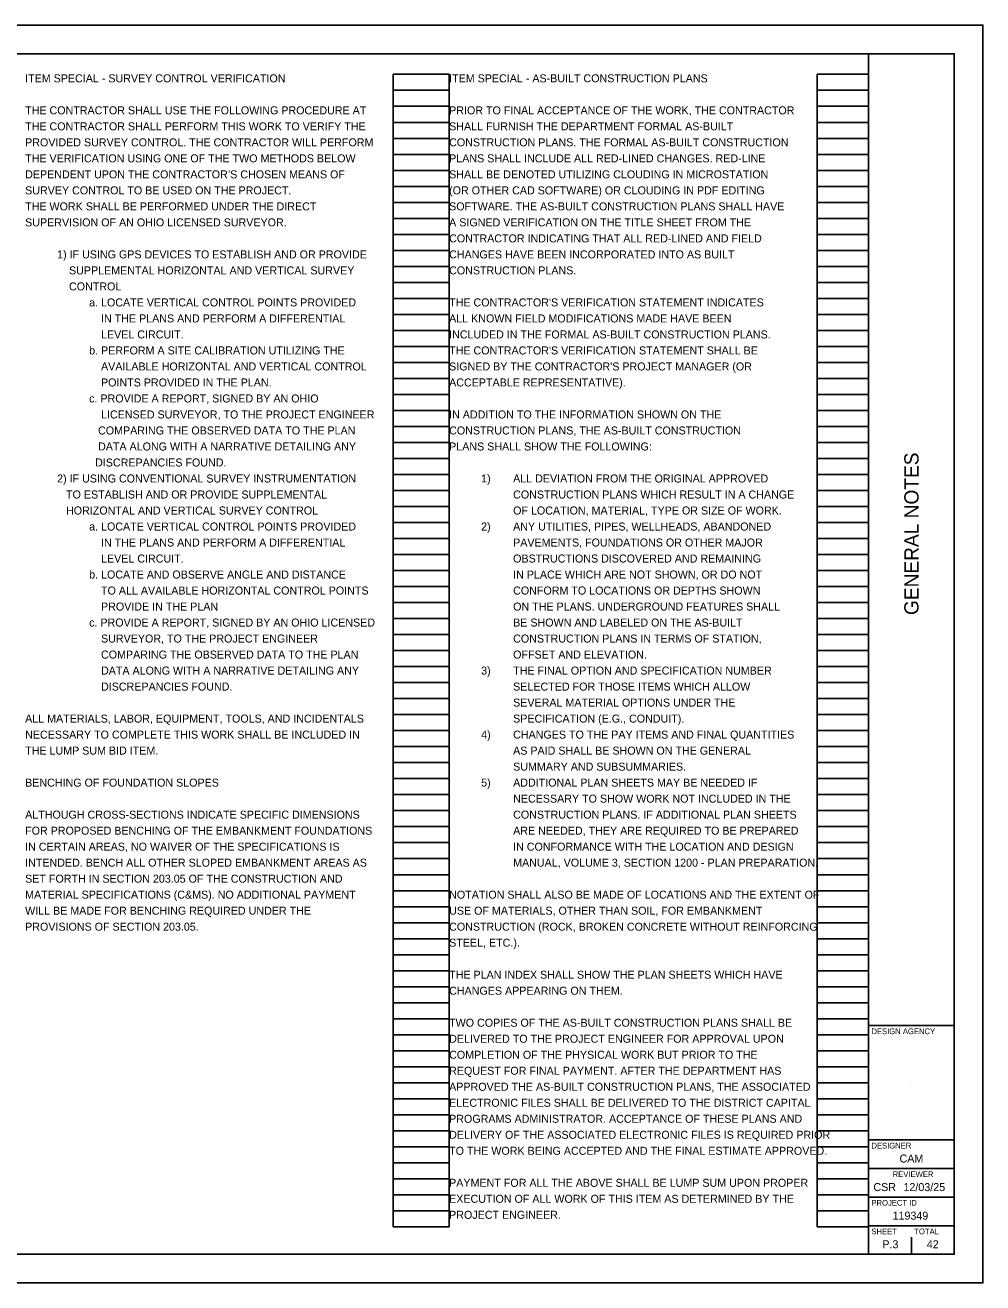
# Model space of a CAD drawing. Extents: x 0 to 34, y 0 to 22.
# Drawn here: x 17.24 to 34, y 0 to 22 of the extents above; entities that cross this region are included whole.
import ezdxf

# ---------------------------------------------------------------- set-up
doc = ezdxf.new("R2010")
doc.units = 0
for name, color, linetype in [('SH_Border', 7, 'Continuous'), ('SH_Cut_Line', 7, 'Continuous'), ('SH_Data', 7, 'Continuous'), ('SH_Text', 7, 'Continuous')]:
    doc.layers.add(name, color=color, linetype=linetype)

msp = doc.modelspace()

# ---------------------------------------------------------------- linework, layer by layer
at = {"layer": 'SH_Border'}
for p, q in [((32, 0.5), (32, 21.5)), ((32, 4.5), (33.5, 4.5)), ((32, 2.5), (33.5, 2.5)), ((32, 2), (33.5, 2)), ((32, 1.5), (33.5, 1.5)), ((32, 1), (33.5, 1))]:
    msp.add_line(p, q, dxfattribs=at)
msp.add_lwpolyline([(1.5, 21.5), (33.5, 21.5), (33.5, 0.5), (1.5, 0.5)], close=True, dxfattribs=at)
at = {"layer": 'SH_Cut_Line'}
msp.add_lwpolyline([(0, 0), (34, 0), (34, 22), (0, 22)], close=True, dxfattribs=at)
at = {"layer": 'SH_Data'}
for p, q in [((23.68, 0.98), (23.68, 21.14)), ((23.68, 21.14), (24.66, 21.14)), ((24.66, 0.98), (24.66, 21.14)), ((31.1, 0.98), (31.1, 21.14)), ((31.1, 21.14), (32, 21.14)), ((32, 0.98), (32, 21.14)), ((23.68, 20.86), (24.66, 20.86)), ((31.1, 20.86), (32, 20.86)), ((23.68, 20.58), (24.66, 20.58)), ((31.1, 20.58), (32, 20.58)), ((23.68, 20.3), (24.66, 20.3)), ((31.1, 20.3), (32, 20.3)), ((23.68, 20.02), (24.66, 20.02)), ((31.1, 20.02), (32, 20.02)), ((23.68, 19.74), (24.66, 19.74)), ((31.1, 19.74), (32, 19.74)), ((23.68, 19.46), (24.66, 19.46)), ((31.1, 19.46), (32, 19.46)), ((23.68, 19.18), (24.66, 19.18)), ((31.1, 19.18), (32, 19.18)), ((23.68, 18.9), (24.66, 18.9)), ((31.1, 18.9), (32, 18.9)), ((23.68, 18.62), (24.66, 18.62)), ((31.1, 18.62), (32, 18.62)), ((23.68, 18.34), (24.66, 18.34)), ((31.1, 18.34), (32, 18.34)), ((23.68, 18.06), (24.66, 18.06)), ((31.1, 18.06), (32, 18.06)), ((23.68, 17.78), (24.66, 17.78)), ((31.1, 17.78), (32, 17.78)), ((23.68, 17.5), (24.66, 17.5)), ((31.1, 17.5), (32, 17.5)), ((23.68, 17.22), (24.66, 17.22)), ((31.1, 17.22), (32, 17.22)), ((23.68, 16.94), (24.66, 16.94)), ((31.1, 16.94), (32, 16.94)), ((23.68, 16.66), (24.66, 16.66)), ((31.1, 16.66), (32, 16.66)), ((23.68, 16.38), (24.66, 16.38)), ((31.1, 16.38), (32, 16.38)), ((23.68, 16.1), (24.66, 16.1)), ((31.1, 16.1), (32, 16.1)), ((23.68, 15.82), (24.66, 15.82)), ((31.1, 15.82), (32, 15.82)), ((23.68, 15.54), (24.66, 15.54)), ((31.1, 15.54), (32, 15.54)), ((23.68, 15.26), (24.66, 15.26)), ((31.1, 15.26), (32, 15.26)), ((23.68, 14.98), (24.66, 14.98)), ((31.1, 14.98), (32, 14.98)), ((23.68, 14.7), (24.66, 14.7)), ((31.1, 14.7), (32, 14.7)), ((23.68, 14.42), (24.66, 14.42)), ((31.1, 14.42), (32, 14.42)), ((23.68, 14.14), (24.66, 14.14)), ((31.1, 14.14), (32, 14.14)), ((23.68, 13.86), (24.66, 13.86)), ((31.1, 13.86), (32, 13.86)), ((23.68, 13.58), (24.66, 13.58)), ((31.1, 13.58), (32, 13.58)), ((23.68, 13.3), (24.66, 13.3)), ((31.1, 13.3), (32, 13.3)), ((23.68, 13.02), (24.66, 13.02)), ((31.1, 13.02), (32, 13.02)), ((23.68, 12.74), (24.66, 12.74)), ((31.1, 12.74), (32, 12.74)), ((23.68, 12.46), (24.66, 12.46)), ((31.1, 12.46), (32, 12.46)), ((23.68, 12.18), (24.66, 12.18)), ((31.1, 12.18), (32, 12.18)), ((23.68, 11.9), (24.66, 11.9)), ((31.1, 11.9), (32, 11.9)), ((23.68, 11.62), (24.66, 11.62)), ((31.1, 11.62), (32, 11.62)), ((23.68, 11.34), (24.66, 11.34)), ((31.1, 11.34), (32, 11.34)), ((23.68, 11.06), (24.66, 11.06)), ((31.1, 11.06), (32, 11.06)), ((23.68, 10.78), (24.66, 10.78)), ((31.1, 10.78), (32, 10.78)), ((23.68, 10.5), (24.66, 10.5)), ((31.1, 10.5), (32, 10.5)), ((23.68, 10.22), (24.66, 10.22)), ((31.1, 10.22), (32, 10.22)), ((23.68, 9.94), (24.66, 9.94)), ((31.1, 9.94), (32, 9.94)), ((23.68, 9.66), (24.66, 9.66)), ((31.1, 9.66), (32, 9.66)), ((23.68, 9.38), (24.66, 9.38)), ((31.1, 9.38), (32, 9.38)), ((23.68, 9.1), (24.66, 9.1)), ((31.1, 9.1), (32, 9.1)), ((23.68, 8.82), (24.66, 8.82)), ((31.1, 8.82), (32, 8.82)), ((23.68, 8.54), (24.66, 8.54)), ((31.1, 8.54), (32, 8.54)), ((23.68, 8.26), (24.66, 8.26)), ((31.1, 8.26), (32, 8.26)), ((23.68, 7.98), (24.66, 7.98)), ((31.1, 7.98), (32, 7.98)), ((23.68, 7.7), (24.66, 7.7)), ((31.1, 7.7), (32, 7.7)), ((23.68, 7.42), (24.66, 7.42)), ((31.1, 7.42), (32, 7.42)), ((23.68, 7.14), (24.66, 7.14)), ((31.1, 7.14), (32, 7.14)), ((23.68, 6.86), (24.66, 6.86)), ((31.1, 6.86), (32, 6.86)), ((23.68, 6.58), (24.66, 6.58)), ((31.1, 6.58), (32, 6.58)), ((23.68, 6.3), (24.66, 6.3)), ((31.1, 6.3), (32, 6.3)), ((23.68, 6.02), (24.66, 6.02)), ((31.1, 6.02), (32, 6.02)), ((23.68, 5.74), (24.66, 5.74)), ((31.1, 5.74), (32, 5.74)), ((23.68, 5.46), (24.66, 5.46)), ((31.1, 5.46), (32, 5.46)), ((23.68, 5.18), (24.66, 5.18)), ((31.1, 5.18), (32, 5.18)), ((23.68, 4.9), (24.66, 4.9)), ((31.1, 4.9), (32, 4.9)), ((23.68, 4.62), (24.66, 4.62)), ((31.1, 4.62), (32, 4.62)), ((23.68, 4.34), (24.66, 4.34)), ((31.1, 4.34), (32, 4.34)), ((23.68, 4.06), (24.66, 4.06)), ((31.1, 4.06), (32, 4.06)), ((23.68, 3.78), (24.66, 3.78)), ((31.1, 3.78), (32, 3.78)), ((23.68, 3.5), (24.66, 3.5)), ((31.1, 3.5), (32, 3.5)), ((32.75, 3.5), (32.75, 3.5)), ((23.68, 3.22), (24.66, 3.22)), ((31.1, 3.22), (32, 3.22)), ((23.68, 2.94), (24.66, 2.94)), ((31.1, 2.94), (32, 2.94)), ((23.68, 2.66), (24.66, 2.66)), ((31.1, 2.66), (32, 2.66)), ((23.68, 2.38), (24.66, 2.38)), ((31.1, 2.38), (32, 2.38)), ((23.68, 2.1), (24.66, 2.1)), ((31.1, 2.1), (32, 2.1)), ((23.68, 1.82), (24.66, 1.82)), ((31.1, 1.82), (32, 1.82)), ((23.68, 1.54), (24.66, 1.54)), ((31.1, 1.54), (32, 1.54)), ((23.68, 1.26), (24.66, 1.26)), ((31.1, 1.26), (32, 1.26)), ((23.68, 0.98), (24.66, 0.98)), ((31.1, 0.98), (32, 0.98)), ((32.375, 0.675), (32.375, 0.675)), ((32.75, 0.5), (32.75, 0.8))]:
    msp.add_line(p, q, dxfattribs=at)

# ---------------------------------------------------------------- texts
msp.add_text('GENERAL NOTES', height=0.25, rotation=90, dxfattribs=at).set_placement((32.875, 11.682))
for s, height, p in [('DESIGN AGENCY', 0.1, (32.05, 4.35)), ('DESIGNER', 0.1, (32.05, 2.35)), ('CAM', 0.14, (32.542, 2.105)), ('REVIEWER', 0.1, (32.422, 1.85)), ('CSR', 0.14, (32.085, 1.605)), ('12/03/25', 0.14, (32.611, 1.605)), ('PROJECT ID', 0.1, (32.05, 1.35)), ('119349', 0.14, (32.42, 1.105)), ('SHEET', 0.1, (32.05, 0.85)), ('TOTAL', 0.1, (32.8, 0.85)), ('P.3', 0.14, (32.241, 0.605)), ('42', 0.14, (33.019, 0.605))]:
    msp.add_text(s, height=height, dxfattribs=at).set_placement(p)
at = {"layer": 'SH_Text'}
for s, p in [('ITEM SPECIAL - SURVEY CONTROL VERIFICATION', (17.24, 21)), ('ITEM SPECIAL - AS-BUILT CONSTRUCTION PLANS', (24.66, 21)), ('THE CONTRACTOR SHALL USE THE FOLLOWING PROCEDURE AT', (17.24, 20.44)), ('PRIOR TO FINAL ACCEPTANCE OF THE WORK, THE CONTRACTOR', (24.66, 20.44)), ('THE CONTRACTOR SHALL PERFORM THIS WORK TO VERIFY THE ', (17.24, 20.16)), ('SHALL FURNISH THE DEPARTMENT FORMAL AS-BUILT  ', (24.66, 20.16)), ('PROVIDED SURVEY CONTROL. THE CONTRACTOR WILL PERFORM ', (17.24, 19.88)), ('CONSTRUCTION PLANS. THE FORMAL AS-BUILT CONSTRUCTION', (24.66, 19.88)), ('THE VERIFICATION USING ONE OF THE TWO METHODS BELOW', (17.24, 19.6)), ('PLANS SHALL INCLUDE ALL RED-LINED CHANGES. RED-LINE', (24.66, 19.6)), ('DEPENDENT UPON THE CONTRACTOR’S CHOSEN MEANS OF ', (17.24, 19.32)), ('SHALL BE DENOTED UTILIZING CLOUDING IN MICROSTATION', (24.66, 19.32)), ('SURVEY CONTROL TO BE USED ON THE PROJECT.  ', (17.24, 19.04)), ('(OR OTHER CAD SOFTWARE) OR CLOUDING IN PDF EDITING', (24.66, 19.04)), ('THE WORK SHALL BE PERFORMED UNDER THE DIRECT', (17.24, 18.76)), ('SOFTWARE. THE AS-BUILT CONSTRUCTION PLANS SHALL HAVE', (24.66, 18.76)), ('SUPERVISION OF AN OHIO LICENSED SURVEYOR.', (17.24, 18.48)), ('A SIGNED VERIFICATION ON THE TITLE SHEET FROM THE', (24.66, 18.48)), ('CONTRACTOR INDICATING THAT ALL RED-LINED AND FIELD', (24.66, 18.2)), ('1) IF USING GPS DEVICES TO ESTABLISH AND OR PROVIDE ', (17.8, 17.92)), ('CHANGES HAVE BEEN INCORPORATED INTO AS BUILT', (24.66, 17.92)), ('    SUPPLEMENTAL HORIZONTAL AND VERTICAL SURVEY', (17.8, 17.64)), ('CONSTRUCTION PLANS.', (24.66, 17.64)), ('    CONTROL ', (17.8, 17.36)), ('a. LOCATE VERTICAL CONTROL POINTS PROVIDED', (18.36, 17.08)), ("THE CONTRACTOR'S VERIFICATION STATEMENT INDICATES", (24.66, 17.08)), ('    IN THE PLANS AND PERFORM A DIFFERENTIAL ', (18.36, 16.8)), ('ALL KNOWN FIELD MODIFICATIONS MADE HAVE BEEN', (24.66, 16.8)), ('    LEVEL CIRCUIT.  ', (18.36, 16.52)), ('INCLUDED IN THE FORMAL AS-BUILT CONSTRUCTION PLANS.', (24.66, 16.52)), ('b. PERFORM A SITE CALIBRATION UTILIZING THE ', (18.36, 16.24)), ("THE CONTRACTOR'S VERIFICATION STATEMENT SHALL BE ", (24.66, 16.24)), ('    AVAILABLE HORIZONTAL AND VERTICAL CONTROL ', (18.36, 15.96)), ("SIGNED BY THE CONTRACTOR'S PROJECT MANAGER (OR", (24.66, 15.96)), ('    POINTS PROVIDED IN THE PLAN.  ', (18.36, 15.68)), ('ACCEPTABLE REPRESENTATIVE).', (24.66, 15.68)), ('c. PROVIDE A REPORT, SIGNED BY AN OHIO', (18.36, 15.4)), ('    LICENSED SURVEYOR, TO THE PROJECT ENGINEER', (18.36, 15.12)), ('IN ADDITION TO THE INFORMATION SHOWN ON THE', (24.66, 15.12)), ('   COMPARING THE OBSERVED DATA TO THE PLAN', (18.36, 14.84)), ('CONSTRUCTION PLANS, THE AS-BUILT CONSTRUCTION', (24.66, 14.84)), ('   DATA ALONG WITH A NARRATIVE DETAILING ANY', (18.36, 14.56)), ('PLANS SHALL SHOW THE FOLLOWING:', (24.66, 14.56)), ('  DISCREPANCIES FOUND. ', (18.36, 14.28)), ('2) IF USING CONVENTIONAL SURVEY INSTRUMENTATION', (17.8, 14)), ('1) ', (25.22, 14)), ('ALL DEVIATION FROM THE ORIGINAL APPROVED', (25.78, 14)), ('   TO ESTABLISH AND OR PROVIDE SUPPLEMENTAL', (17.8, 13.72)), ('CONSTRUCTION PLANS WHICH RESULT IN A CHANGE', (25.78, 13.72)), ('   HORIZONTAL AND VERTICAL SURVEY CONTROL ', (17.8, 13.44)), ('OF LOCATION, MATERIAL, TYPE OR SIZE OF WORK.', (25.78, 13.44)), ('a. LOCATE VERTICAL CONTROL POINTS PROVIDED', (18.36, 13.16)), ('2)', (25.22, 13.16)), ('ANY UTILITIES, PIPES, WELLHEADS, ABANDONED', (25.78, 13.16)), ('    IN THE PLANS AND PERFORM A DIFFERENTIAL ', (18.36, 12.88)), ('PAVEMENTS, FOUNDATIONS OR OTHER MAJOR', (25.78, 12.88)), ('    LEVEL CIRCUIT.  ', (18.36, 12.6)), ('OBSTRUCTIONS DISCOVERED AND REMAINING', (25.78, 12.6)), ('b. LOCATE AND OBSERVE ANGLE AND DISTANCE', (18.36, 12.32)), ('IN PLACE WHICH ARE NOT SHOWN, OR DO NOT', (25.78, 12.32)), ('    TO ALL AVAILABLE HORIZONTAL CONTROL POINTS', (18.36, 12.04)), ('CONFORM TO LOCATIONS OR DEPTHS SHOWN', (25.78, 12.04)), ('    PROVIDE IN THE PLAN ', (18.36, 11.76)), ('ON THE PLANS. UNDERGROUND FEATURES SHALL', (25.78, 11.76)), ('c. PROVIDE A REPORT, SIGNED BY AN OHIO LICENSED', (18.36, 11.48)), ('BE SHOWN AND LABELED ON THE AS-BUILT', (25.78, 11.48)), ('    SURVEYOR, TO THE PROJECT ENGINEER', (18.36, 11.2)), ('CONSTRUCTION PLANS IN TERMS OF STATION,', (25.78, 11.2)), ('    COMPARING THE OBSERVED DATA TO THE PLAN', (18.36, 10.92)), ('OFFSET AND ELEVATION.', (25.78, 10.92)), ('    DATA ALONG WITH A NARRATIVE DETAILING ANY', (18.36, 10.64)), ('3)', (25.22, 10.64)), ('THE FINAL OPTION AND SPECIFICATION NUMBER', (25.78, 10.64)), ('    DISCREPANCIES FOUND. ', (18.36, 10.36)), ('SELECTED FOR THOSE ITEMS WHICH ALLOW', (25.78, 10.36)), ('SEVERAL MATERIAL OPTIONS UNDER THE', (25.78, 10.08)), ('ALL MATERIALS, LABOR, EQUIPMENT, TOOLS, AND INCIDENTALS', (17.24, 9.8)), ('SPECIFICATION (E.G., CONDUIT).', (25.78, 9.8)), ('NECESSARY TO COMPLETE THIS WORK SHALL BE INCLUDED IN', (17.24, 9.52)), ('4)', (25.22, 9.52)), ('CHANGES TO THE PAY ITEMS AND FINAL QUANTITIES', (25.78, 9.52)), ('THE LUMP SUM BID ITEM.', (17.24, 9.24)), ('AS PAID SHALL BE SHOWN ON THE GENERAL', (25.78, 9.24)), ('SUMMARY AND SUBSUMMARIES.', (25.78, 8.96)), ('BENCHING OF FOUNDATION SLOPES', (17.24, 8.68)), ('5)', (25.22, 8.68)), ('ADDITIONAL PLAN SHEETS MAY BE NEEDED IF', (25.78, 8.68)), ('NECESSARY TO SHOW WORK NOT INCLUDED IN THE', (25.78, 8.4)), ('ALTHOUGH CROSS-SECTIONS INDICATE SPECIFIC DIMENSIONS', (17.24, 8.12)), ('CONSTRUCTION PLANS. IF ADDITIONAL PLAN SHEETS', (25.78, 8.12)), ('FOR PROPOSED BENCHING OF THE EMBANKMENT FOUNDATIONS', (17.24, 7.84)), ('ARE NEEDED, THEY ARE REQUIRED TO BE PREPARED', (25.78, 7.84)), ('IN CERTAIN AREAS, NO WAIVER OF THE SPECIFICATIONS IS', (17.24, 7.56)), ('IN CONFORMANCE WITH THE LOCATION AND DESIGN', (25.78, 7.56)), ('INTENDED. BENCH ALL OTHER SLOPED EMBANKMENT AREAS AS', (17.24, 7.28)), ('MANUAL, VOLUME 3, SECTION 1200 - PLAN PREPARATION.', (25.78, 7.28)), ('SET FORTH IN SECTION 203.05 OF THE CONSTRUCTION AND', (17.24, 7)), ('MATERIAL SPECIFICATIONS (C&MS). NO ADDITIONAL PAYMENT', (17.24, 6.72)), ('NOTATION SHALL ALSO BE MADE OF LOCATIONS AND THE EXTENT OF', (24.66, 6.72)), ('WILL BE MADE FOR BENCHING REQUIRED UNDER THE', (17.24, 6.44)), ('USE OF MATERIALS, OTHER THAN SOIL, FOR EMBANKMENT', (24.66, 6.44)), ('PROVISIONS OF SECTION 203.05.', (17.24, 6.16)), ('CONSTRUCTION (ROCK, BROKEN CONCRETE WITHOUT REINFORCING', (24.66, 6.16)), ('STEEL, ETC.).', (24.66, 5.88)), ('THE PLAN INDEX SHALL SHOW THE PLAN SHEETS WHICH HAVE', (24.66, 5.32)), ('CHANGES APPEARING ON THEM.', (24.66, 5.04)), ('TWO COPIES OF THE AS-BUILT CONSTRUCTION PLANS SHALL BE', (24.66, 4.48)), ('DELIVERED TO THE PROJECT ENGINEER FOR APPROVAL UPON', (24.66, 4.2)), ('COMPLETION OF THE PHYSICAL WORK BUT PRIOR TO THE', (24.66, 3.92)), ('REQUEST FOR FINAL PAYMENT. AFTER THE DEPARTMENT HAS', (24.66, 3.64)), ('APPROVED THE AS-BUILT CONSTRUCTION PLANS, THE ASSOCIATED', (24.66, 3.36)), ('ELECTRONIC FILES SHALL BE DELIVERED TO THE DISTRICT CAPITAL', (24.66, 3.08)), ('PROGRAMS ADMINISTRATOR. ACCEPTANCE OF THESE PLANS AND', (24.66, 2.8)), ('DELIVERY OF THE ASSOCIATED ELECTRONIC FILES IS REQUIRED PRIOR', (24.66, 2.52)), ('TO THE WORK BEING ACCEPTED AND THE FINAL ESTIMATE APPROVED.', (24.66, 2.24)), ('PAYMENT FOR ALL THE ABOVE SHALL BE LUMP SUM UPON PROPER', (24.66, 1.68)), ('EXECUTION OF ALL WORK OF THIS ITEM AS DETERMINED BY THE', (24.66, 1.4)), ('PROJECT ENGINEER.', (24.66, 1.12))]:
    msp.add_text(s, height=0.14, dxfattribs=at).set_placement(p)

doc.saveas('drawing.dxf')
